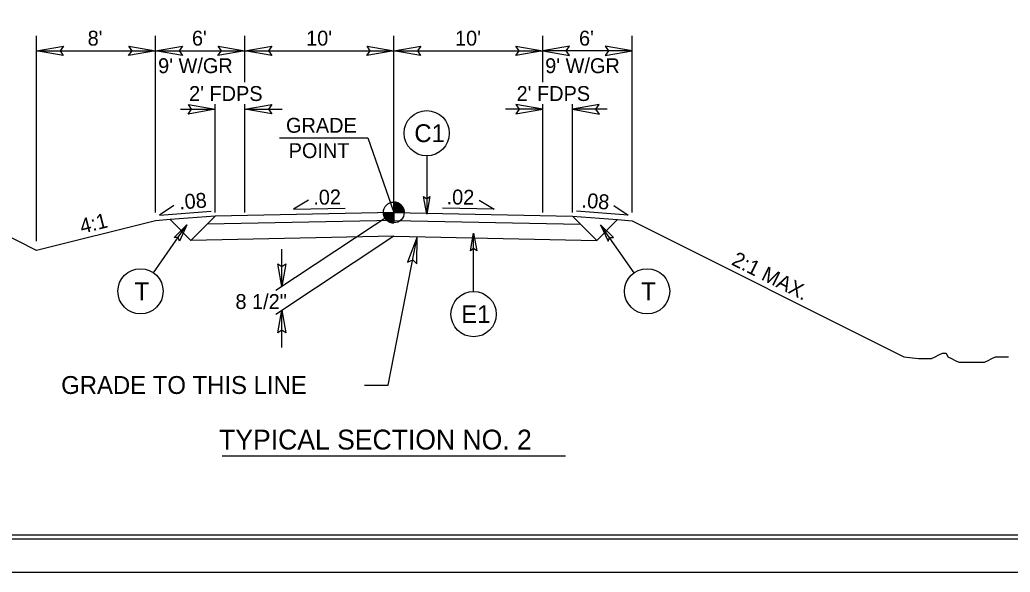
# Model space of a CAD drawing. Extents: x 574216 to 574384, y -52685 to -52551.
# Drawn here: x 574261.2 to 574327.7, y -52685.3 to -52648.2 of the extents above; entities that cross this region are included whole.
import ezdxf

# ---------------------------------------------------------------- set-up
doc = ezdxf.new("R2010")
doc.units = 0
for name, color, linetype in [('Old_Level_1', 7, 'Continuous'), ('Old_Level_15', 7, 'Continuous'), ('Old_Level_2', 7, 'Continuous'), ('Prop DSN Text', 7, 'Continuous'), ('Prop Pavement Schedule Description CELL', 7, 'Continuous'), ('Prop Terminator CELL', 7, 'Continuous'), ('Sheet Cutting Line CELL', 7, 'Continuous'), ('Sheet Plot Border Inside CELL', 7, 'Continuous'), ('Sheet Plot Border Outside CELL', 7, 'Continuous'), ('Sheet Typical CELL', 7, 'Continuous')]:
    doc.layers.add(name, color=color, linetype=linetype)

msp = doc.modelspace()

# ---------------------------------------------------------------- linework, layer by layer
at = {"layer": 'Old_Level_1'}
for p, q in [((574262.322, -52663.02), (574262.322, -52649.247)), ((574270.322, -52661.101), (574270.322, -52649.247)), ((574276.322, -52652.354), (574276.322, -52649.247)), ((574286.322, -52661.101), (574286.322, -52649.247)), ((574296.322, -52652.354), (574296.322, -52649.247)), ((574302.322, -52661.101), (574302.322, -52649.247)), ((574262.322, -52650.247), (574270.322, -52650.247)), ((574270.322, -52650.247), (574276.322, -52650.247)), ((574276.322, -52650.247), (574286.322, -52650.247)), ((574286.322, -52650.247), (574296.322, -52650.247)), ((574302.322, -52650.247), (574296.322, -52650.247)), ((574271.986, -52654.17), (574274.322, -52654.17)), ((574274.322, -52661.101), (574274.322, -52653.833)), ((574276.322, -52661.101), (574276.322, -52653.833)), ((574276.322, -52654.17), (574278.815, -52654.17)), ((574296.322, -52654.17), (574293.828, -52654.17)), ((574296.322, -52661.101), (574296.322, -52653.833)), ((574298.322, -52661.101), (574298.322, -52653.833)), ((574300.657, -52654.17), (574298.322, -52654.17)), ((574262.322, -52663.661), (574252.062, -52658.531)), ((574286.322, -52661.101), (574286.322, -52660.402)), ((574271.297, -52661.583), (574270.322, -52661.661)), ((574274.322, -52661.341), (574271.297, -52661.583)), ((574271.297, -52661.583), (574272.689, -52662.974)), ((574274.322, -52661.341), (574272.689, -52662.974)), ((574286.322, -52661.101), (574274.322, -52661.341)), ((574286.322, -52661.101), (574278.39, -52666.348)), ((574285.622, -52661.101), (574286.322, -52661.101)), ((574286.32, -52661.801), (574286.322, -52661.101)), ((574286.322, -52661.101), (574286.32, -52661.801)), ((574287.021, -52661.101), (574286.322, -52661.101)), ((574286.322, -52661.101), (574298.322, -52661.341)), ((574298.322, -52661.341), (574299.954, -52662.974)), ((574298.322, -52661.341), (574301.346, -52661.583)), ((574301.346, -52661.583), (574299.954, -52662.974)), ((574301.346, -52661.583), (574302.322, -52661.661)), ((574270.322, -52661.661), (574262.322, -52663.661)), ((574286.318, -52661.631), (574273.781, -52661.882)), ((574286.326, -52661.631), (574298.862, -52661.882)), ((574302.322, -52661.661), (574320.581, -52670.791)), ((574286.318, -52662.702), (574272.689, -52662.974)), ((574286.322, -52662.702), (574278.39, -52667.948)), ((574286.326, -52662.702), (574299.954, -52662.974)), ((574278.807, -52666.063), (574278.807, -52663.563)), ((574278.807, -52670.164), (574278.807, -52667.664)), ((574274.784, -52677.436), (574297.858, -52677.436))]:
    msp.add_line(p, q, dxfattribs=at)
for points in [[(574280.586, -52660.281), (574279.584, -52660.886), (574283.06, -52660.816)], [(574292.06, -52660.281), (574293.063, -52660.886), (574289.587, -52660.817)], [(574271.553, -52660.625), (574270.589, -52661.289), (574274.054, -52661.012)], [(574286.328, -52660.402), (574286.328, -52660.402), (574286.328, -52661.101)], [(574286.342, -52660.402), (574286.342, -52661.101)], [(574286.356, -52660.403), (574286.356, -52661.101)], [(574286.37, -52660.403), (574286.37, -52661.101)], [(574286.384, -52660.405), (574286.384, -52661.101)], [(574286.398, -52660.406), (574286.398, -52661.101)], [(574286.412, -52660.408), (574286.412, -52661.101)], [(574286.426, -52660.41), (574286.426, -52661.101)], [(574286.44, -52660.411), (574286.44, -52661.101)], [(574286.454, -52660.414), (574286.454, -52661.101)], [(574286.468, -52660.417), (574286.468, -52661.101)], [(574286.482, -52660.42), (574286.482, -52661.101)], [(574286.496, -52660.424), (574286.496, -52661.101)], [(574286.51, -52660.428), (574286.51, -52661.101)], [(574286.524, -52660.431), (574286.524, -52661.101)], [(574286.538, -52660.436), (574286.538, -52661.101)], [(574286.552, -52660.441), (574286.552, -52661.101)], [(574286.566, -52660.445), (574286.566, -52661.101)], [(574286.58, -52660.452), (574286.58, -52661.101)], [(574286.594, -52660.458), (574286.594, -52661.101)], [(574286.608, -52660.464), (574286.608, -52661.101)], [(574286.622, -52660.47), (574286.622, -52661.101)], [(574286.636, -52660.476), (574286.636, -52661.101)], [(574286.649, -52660.484), (574286.649, -52661.101)], [(574286.663, -52660.492), (574286.663, -52661.101)], [(574286.677, -52660.5), (574286.677, -52661.101)], [(574286.691, -52660.507), (574286.691, -52661.101)], [(574286.705, -52660.517), (574286.705, -52661.101)], [(574286.719, -52660.526), (574286.719, -52661.101)], [(574286.733, -52660.537), (574286.733, -52661.101)], [(574286.747, -52660.546), (574286.747, -52661.101)], [(574286.761, -52660.557), (574286.761, -52661.101)], [(574286.775, -52660.57), (574286.775, -52661.101)], [(574286.789, -52660.582), (574286.789, -52661.101)], [(574286.803, -52660.595), (574286.803, -52661.101)], [(574286.817, -52660.609), (574286.817, -52661.101)], [(574286.831, -52660.623), (574286.831, -52661.101)], [(574286.845, -52660.638), (574286.845, -52661.101)], [(574286.859, -52660.655), (574286.859, -52661.101)], [(574286.873, -52660.672), (574286.873, -52661.101)], [(574286.887, -52660.691), (574286.887, -52661.101)], [(574286.901, -52660.711), (574286.901, -52661.101)], [(574286.915, -52660.733), (574286.915, -52661.101)], [(574286.929, -52660.756), (574286.929, -52661.101)], [(574286.943, -52660.781), (574286.943, -52661.101)], [(574286.957, -52660.811), (574286.957, -52661.101)], [(574286.971, -52660.843), (574286.971, -52661.101)], [(574286.985, -52660.882), (574286.985, -52661.101)], [(574286.999, -52660.93), (574286.999, -52661.101)], [(574301.09, -52660.625), (574302.054, -52661.289), (574298.589, -52661.012)], [(574285.625, -52661.101), (574285.625, -52661.177)], [(574285.639, -52661.101), (574285.639, -52661.26)], [(574285.653, -52661.101), (574285.653, -52661.31)], [(574285.667, -52661.101), (574285.667, -52661.352)], [(574285.681, -52661.101), (574285.681, -52661.384)], [(574285.695, -52661.101), (574285.695, -52661.414)], [(574285.709, -52661.101), (574285.709, -52661.44)], [(574285.723, -52661.101), (574285.723, -52661.465)], [(574285.737, -52661.101), (574285.737, -52661.487)], [(574285.751, -52661.101), (574285.751, -52661.507)], [(574285.765, -52661.101), (574285.765, -52661.526)], [(574285.779, -52661.101), (574285.779, -52661.543)], [(574285.793, -52661.101), (574285.793, -52661.56)], [(574285.807, -52661.101), (574285.807, -52661.575)], [(574285.821, -52661.101), (574285.821, -52661.591)], [(574285.835, -52661.101), (574285.835, -52661.605)], [(574285.849, -52661.101), (574285.849, -52661.617)], [(574285.863, -52661.101), (574285.863, -52661.63)], [(574285.877, -52661.101), (574285.877, -52661.642)], [(574285.891, -52661.101), (574285.891, -52661.653)], [(574285.905, -52661.101), (574285.905, -52661.664)], [(574285.919, -52661.101), (574285.919, -52661.673)], [(574285.933, -52661.101), (574285.933, -52661.683)], [(574285.947, -52661.101), (574285.947, -52661.692)], [(574285.961, -52661.101), (574285.961, -52661.701)], [(574285.975, -52661.101), (574285.975, -52661.709)], [(574285.989, -52661.101), (574285.989, -52661.717)], [(574286.003, -52661.101), (574286.003, -52661.725)], [(574286.017, -52661.101), (574286.017, -52661.731)], [(574286.031, -52661.101), (574286.031, -52661.737)], [(574286.045, -52661.101), (574286.045, -52661.743)], [(574286.059, -52661.101), (574286.059, -52661.749)], [(574286.073, -52661.101), (574286.073, -52661.756)], [(574286.087, -52661.101), (574286.087, -52661.76)], [(574286.101, -52661.101), (574286.101, -52661.765)], [(574286.115, -52661.101), (574286.115, -52661.77)], [(574286.129, -52661.101), (574286.129, -52661.773)], [(574286.143, -52661.101), (574286.143, -52661.777)], [(574286.157, -52661.101), (574286.157, -52661.78)], [(574286.171, -52661.101), (574286.171, -52661.784)], [(574286.185, -52661.101), (574286.185, -52661.787)], [(574286.199, -52661.101), (574286.199, -52661.79)], [(574286.213, -52661.101), (574286.213, -52661.791)], [(574286.227, -52661.101), (574286.227, -52661.794)], [(574286.241, -52661.101), (574286.241, -52661.796)], [(574286.255, -52661.101), (574286.255, -52661.798)], [(574286.269, -52661.101), (574286.269, -52661.799)], [(574286.283, -52661.101), (574286.283, -52661.799)], [(574286.297, -52661.101), (574286.297, -52661.801)], [(574286.311, -52661.101), (574286.311, -52661.801), (574286.311, -52661.801)], [(574287.013, -52661.002), (574287.013, -52661.101)], [(574320.581, -52670.791), (574321.567, -52670.914), (574321.813, -52670.914), (574322.183, -52670.914), (574322.43, -52670.914), (574322.676, -52670.791), (574322.922, -52670.668), (574323.169, -52670.544), (574323.415, -52670.544), (574323.539, -52670.791), (574323.785, -52670.914), (574324.031, -52671.038), (574324.278, -52671.16), (574324.524, -52671.16), (574324.771, -52671.16), (574325.017, -52671.16), (574325.263, -52671.16), (574325.51, -52671.16), (574325.756, -52671.16), (574326.002, -52671.16), (574326.249, -52671.038), (574326.495, -52670.914), (574326.742, -52670.791), (574327.112, -52670.791), (574327.358, -52670.791), (574327.604, -52670.791)]]:
    msp.add_lwpolyline(points, dxfattribs=at)
msp.add_circle((574286.321, -52661.101), 0.699, dxfattribs=at)
for start, end in [(359.99048, 89.99048), (179.99048, 269.99048)]:
    msp.add_arc((574286.321, -52661.101), 0.699, start, end, dxfattribs=at)
at = {"layer": 'Old_Level_15'}
for p, q in [((574278.644, -52656.099), (574284.576, -52656.099)), ((574284.576, -52656.099), (574286.322, -52661.101)), ((574285.947, -52672.694), (574287.901, -52662.733)), ((574284.352, -52672.694), (574285.947, -52672.694))]:
    msp.add_line(p, q, dxfattribs=at)
at = {"layer": 'Old_Level_2'}
for p, q in [((574288.532, -52657.297), (574288.531, -52661.222)), ((574270.178, -52665.15), (574272.429, -52661.935)), ((574302.465, -52665.15), (574300.214, -52661.935)), ((574291.68, -52666.41), (574291.68, -52662.486))]:
    msp.add_line(p, q, dxfattribs=at)
for points in [[(574288.323, -52660.032), (574288.532, -52660.178), (574288.74, -52660.032), (574288.531, -52661.222)], [(574271.918, -52663.029), (574271.83, -52662.79), (574271.576, -52662.79), (574272.429, -52661.935)], [(574300.725, -52663.029), (574300.813, -52662.79), (574301.067, -52662.79), (574300.214, -52661.935)], [(574291.889, -52663.675), (574291.68, -52663.529), (574291.472, -52663.675), (574291.68, -52662.486)]]:
    msp.add_lwpolyline(points, close=True, dxfattribs=at)
for centre in [(574288.532, -52655.778), (574269.307, -52666.394), (574303.336, -52666.394), (574291.68, -52667.929)]:
    msp.add_circle(centre, 1.519, dxfattribs=at)
at = {"layer": 'Prop DSN Text'}
for points in [[(574279.074, -52664.542), (574278.807, -52666.063), (574278.54, -52664.542), (574278.807, -52664.729)], [(574278.54, -52669.184), (574278.807, -52667.664), (574279.074, -52669.184), (574278.807, -52668.998)]]:
    msp.add_lwpolyline(points, close=True, dxfattribs=at)
at = {"layer": 'Prop Terminator CELL'}
for points in [[(574264.122, -52650.557), (574262.322, -52650.247), (574264.132, -52649.927), (574263.902, -52650.247)], [(574268.522, -52649.937), (574270.322, -52650.247), (574268.512, -52650.567), (574268.742, -52650.247)], [(574272.122, -52650.557), (574270.322, -52650.247), (574272.132, -52649.927), (574271.902, -52650.247)], [(574274.522, -52649.937), (574276.322, -52650.247), (574274.512, -52650.567), (574274.742, -52650.247)], [(574278.122, -52650.557), (574276.322, -52650.247), (574278.132, -52649.927), (574277.902, -52650.247)], [(574284.522, -52649.937), (574286.322, -52650.247), (574284.512, -52650.567), (574284.742, -52650.247)], [(574288.122, -52650.557), (574286.322, -52650.247), (574288.132, -52649.927), (574287.902, -52650.247)], [(574294.522, -52649.937), (574296.322, -52650.247), (574294.512, -52650.567), (574294.742, -52650.247)], [(574298.122, -52649.937), (574296.322, -52650.247), (574298.132, -52650.567), (574297.902, -52650.247)], [(574300.522, -52650.557), (574302.322, -52650.247), (574300.512, -52649.927), (574300.742, -52650.247)], [(574272.522, -52653.86), (574274.322, -52654.17), (574272.512, -52654.49), (574272.742, -52654.17)], [(574278.122, -52654.48), (574276.322, -52654.17), (574278.132, -52653.85), (574277.902, -52654.17)], [(574294.522, -52654.48), (574296.322, -52654.17), (574294.512, -52653.85), (574294.742, -52654.17)], [(574300.122, -52653.86), (574298.322, -52654.17), (574300.132, -52654.49), (574299.902, -52654.17)], [(574287.859, -52664.559), (574287.901, -52662.733), (574287.239, -52664.448), (574287.597, -52664.284)]]:
    msp.add_lwpolyline(points, close=True, dxfattribs=at)
at = {"layer": 'Sheet Cutting Line CELL'}
msp.add_line((574215.577, -52685.254), (574383.977, -52685.254), dxfattribs=at)
at = {"layer": 'Sheet Plot Border Inside CELL'}
msp.add_lwpolyline([(574383.527, -52577.499), (574216.877, -52577.499), (574216.877, -52683.009), (574383.527, -52683.009)], close=True, dxfattribs=at)
at = {"layer": 'Sheet Plot Border Outside CELL'}
msp.add_lwpolyline([(574383.977, -52575.254), (574215.577, -52575.254), (574215.577, -52685.254), (574383.977, -52685.254)], close=True, dxfattribs=at)
at = {"layer": 'Sheet Typical CELL'}
msp.add_lwpolyline([(574382.277, -52577.754), (574232.277, -52577.754), (574232.277, -52682.754), (574382.277, -52682.754)], close=True, dxfattribs=at)

# ---------------------------------------------------------------- texts
at = {"layer": 'Old_Level_1'}
for s, height, p in [("8'", 1, (574265.755, -52649.897)), ("6'", 1, (574272.762, -52649.897)), ("10'", 1, (574280.432, -52649.897)), ("10'", 1, (574290.432, -52649.897)), ("6'", 1, (574298.762, -52649.897)), ("9' W/GR", 1, (574270.491, -52651.747)), ("9' W/GR", 1, (574296.491, -52651.747)), ("2' FDPS", 1, (574272.57, -52653.616)), ("2' FDPS", 1, (574294.57, -52653.616)), ('GRADE', 1, (574279.081, -52655.749)), ('POINT', 1, (574279.258, -52657.449)), ('8 1/2"', 1, (574275.685, -52667.583)), ('GRADE TO THIS LINE', 1.2, (574263.978, -52673.286)), ('TYPICAL SECTION NO. 2', 1.33333, (574274.587, -52677.017))]:
    msp.add_text(s, height=height, dxfattribs=at).set_placement(p)
for s, rotation, p in [('.02', 1.14901, (574280.922, -52660.587)), ('.02', 358.85099, (574289.859, -52660.55)), ('.08', 4.57717, (574271.939, -52660.908)), ('.08', 355.42283, (574298.907, -52660.764)), ('4:1', 14.03624, (574265.373, -52662.538)), ('2:1 MAX.', 333.43495, (574308.939, -52664.579))]:
    msp.add_text(s, height=1, rotation=rotation, dxfattribs=at).set_placement(p)
at = {"layer": 'Prop Pavement Schedule Description CELL'}
for s, p in [('C1', (574287.702, -52656.378)), ('T', (574268.91, -52666.994)), ('T', (574302.94, -52666.994)), ('E1', (574290.85, -52668.529))]:
    msp.add_text(s, height=1.2, dxfattribs=at).set_placement(p)

doc.saveas('drawing.dxf')
